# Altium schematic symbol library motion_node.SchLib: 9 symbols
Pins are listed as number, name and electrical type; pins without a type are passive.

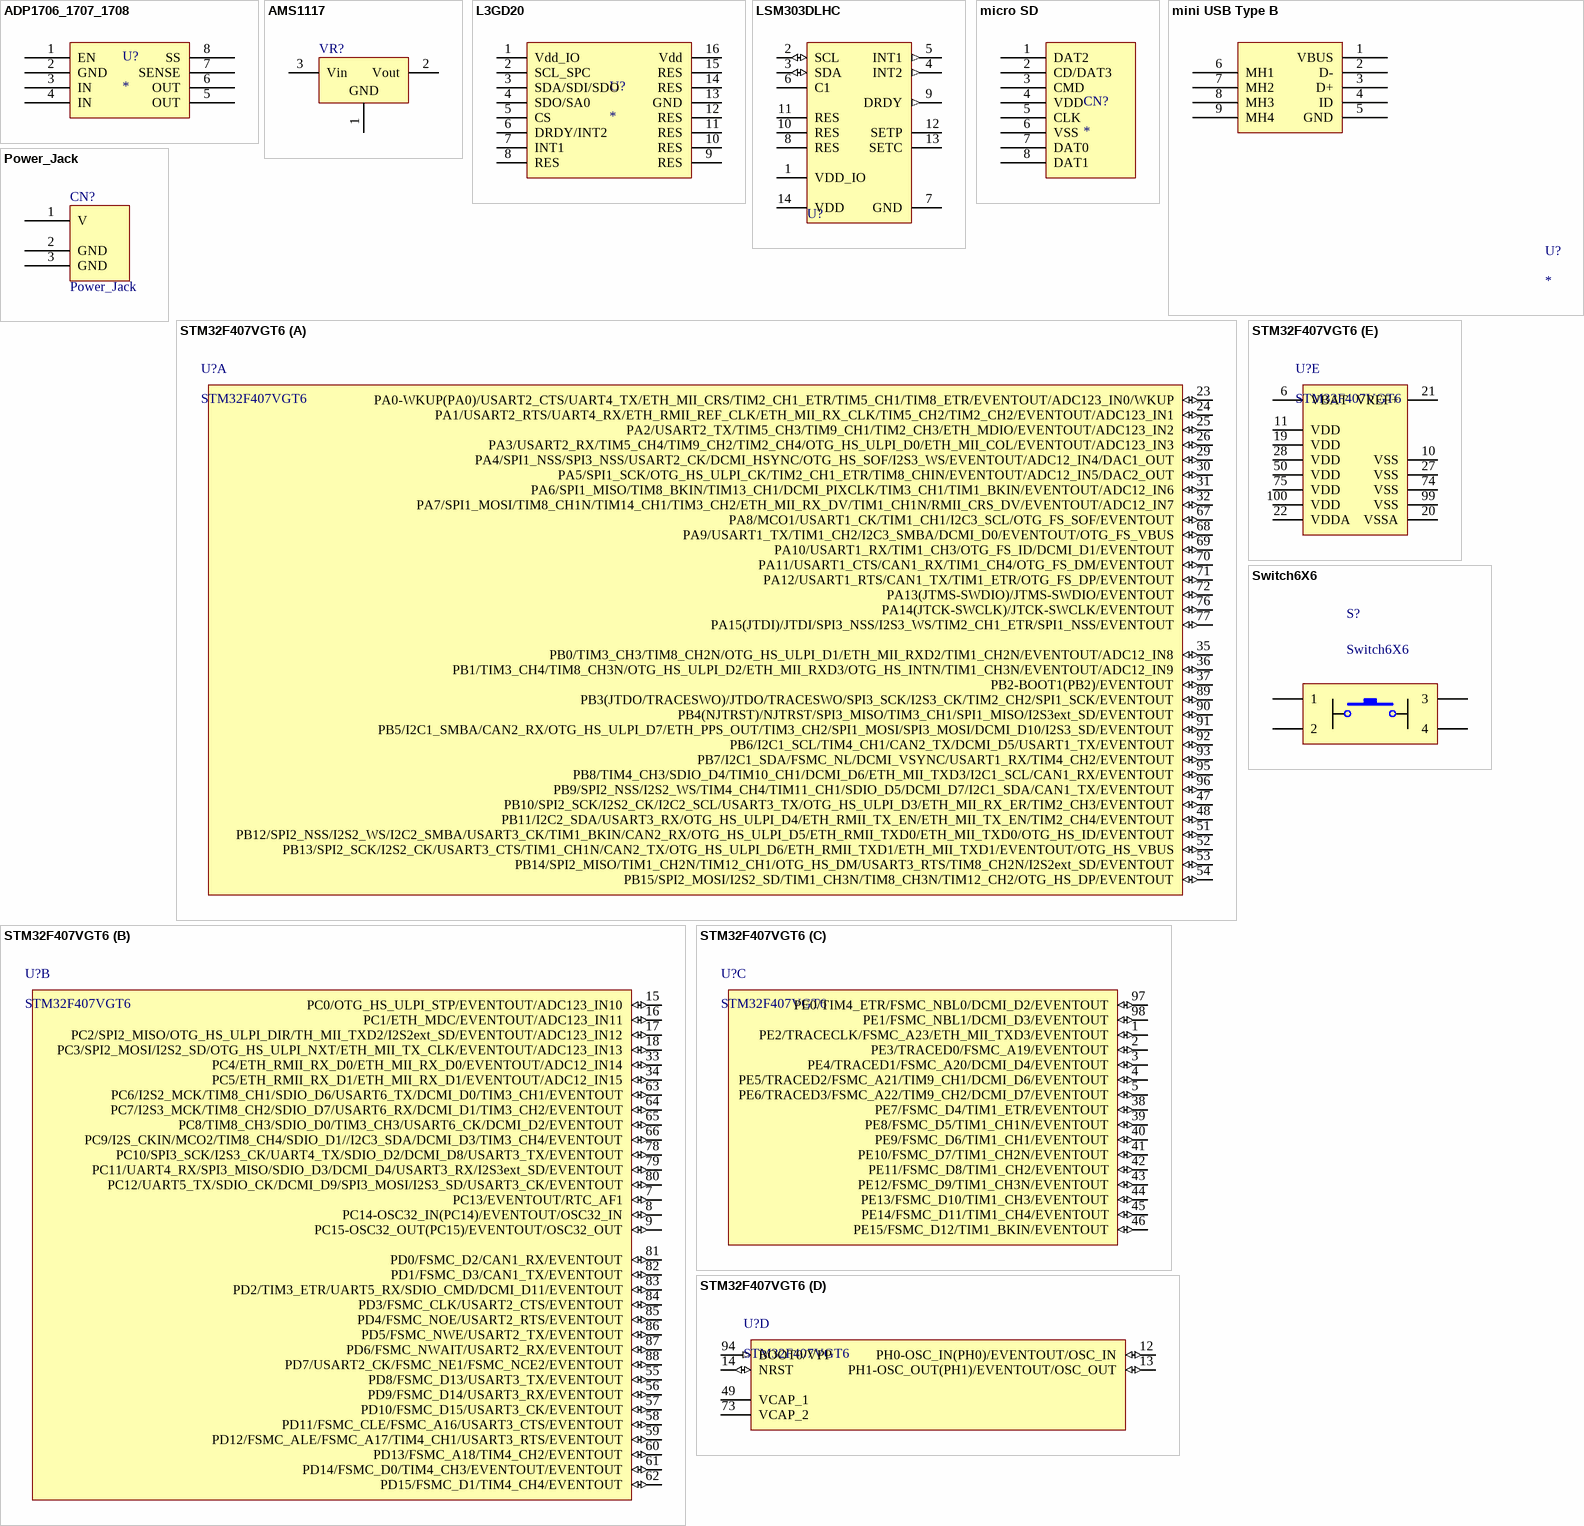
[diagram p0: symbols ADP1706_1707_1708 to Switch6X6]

## ADP1706_1707_1708
designator U?
Linear Regulator
pins: 1 EN, 2 GND, 3 IN, 4 IN, 5 OUT, 6 OUT, 7 SENSE, 8 SS

## AMS1117
designator VR?  (value not drawn)
Voltage Regulator; Code - JEDEC: SMD-220
footprint AMS1117
pins: 1 GND, 2 Vout, 3 Vin

## L3GD20
designator U?
footprint LGA16-4X4X1
pins: 1 Vdd_IO, 2 SCL_SPC, 3 SDA/SDI/SDO, 4 SDO/SA0, 5 CS, 6 DRDY/INT2, 7 INT1, 8 RES, 9 RES, 10 RES, 11 RES, 12 RES, 13 GND, 14 RES, 15 RES, 16 Vdd

## LSM303DLHC
designator U?
footprint LGA14-3X5X1_N (PQFN, 14-Leads, Body 3x5mm, Pitch 0.8mm, IPC Medium Density)
pins: 1 VDD_IO (power), 2 SCL (io), 3 SDA (io), 4 INT2 (out), 5 INT1 (out), 6 C1, 7 GND (power), 8 RES, 9 DRDY (out), 10 RES, 11 RES, 12 SETP, 13 SETC, 14 VDD (power)

## micro SD
designator CN?
footprint micro SD
pins: 1 DAT2, 2 CD/DAT3, 3 CMD, 4 VDD, 5 CLK, 6 VSS, 7 DAT0, 8 DAT1

## mini USB Type B
designator U?
signal-integrity model Mini USB Receptacle (Model Description)
footprint mini USB Type B
pins: 1 VBUS, 2 D-, 3 D+, 4 ID, 5 GND, 6 MH1, 7 MH2, 8 MH3, 9 MH4

## Power_Jack
designator CN?
footprint POWER_JACK
pins: 1 V (power), 2 GND (power), 3 GND (power)

## STM32F407VGT6
designator U?
footprint LQFP100_V (Thin QFP, 100-Leads, Body 14x14mm, Pitch 0.5mm, ST Recommended)
part A pins: 23 PA0-WKUP(PA0)/USART2_CTS/UART4_TX/ETH_MII_CRS/TIM2_CH1_ETR/TIM5_CH1/TIM8_ETR/EVENTOUT/ADC123_IN0/WKUP (io), 24 PA1/USART2_RTS/UART4_RX/ETH_RMII_REF_CLK/ETH_MII_RX_CLK/TIM5_CH2/TIM2_CH2/EVENTOUT/ADC123_IN1 (io), 25 PA2/USART2_TX/TIM5_CH3/TIM9_CH1/TIM2_CH3/ETH_MDIO/EVENTOUT/ADC123_IN2 (io), 26 PA3/USART2_RX/TIM5_CH4/TIM9_CH2/TIM2_CH4/OTG_HS_ULPI_D0/ETH_MII_COL/EVENTOUT/ADC123_IN3 (io), 29 PA4/SPI1_NSS/SPI3_NSS/USART2_CK/DCMI_HSYNC/OTG_HS_SOF/I2S3_WS/EVENTOUT/ADC12_IN4/DAC1_OUT (io), 30 PA5/SPI1_SCK/OTG_HS_ULPI_CK/TIM2_CH1_ETR/TIM8_CHIN/EVENTOUT/ADC12_IN5/DAC2_OUT (io), 31 PA6/SPI1_MISO/TIM8_BKIN/TIM13_CH1/DCMI_PIXCLK/TIM3_CH1/TIM1_BKIN/EVENTOUT/ADC12_IN6 (io), 32 PA7/SPI1_MOSI/TIM8_CH1N/TIM14_CH1/TIM3_CH2/ETH_MII_RX_DV/TIM1_CH1N/RMII_CRS_DV/EVENTOUT/ADC12_IN7 (io), 35 PB0/TIM3_CH3/TIM8_CH2N/OTG_HS_ULPI_D1/ETH_MII_RXD2/TIM1_CH2N/EVENTOUT/ADC12_IN8 (io), 36 PB1/TIM3_CH4/TIM8_CH3N/OTG_HS_ULPI_D2/ETH_MII_RXD3/OTG_HS_INTN/TIM1_CH3N/EVENTOUT/ADC12_IN9 (io), 37 PB2-BOOT1(PB2)/EVENTOUT (io), 47 PB10/SPI2_SCK/I2S2_CK/I2C2_SCL/USART3_TX/OTG_HS_ULPI_D3/ETH_MII_RX_ER/TIM2_CH3/EVENTOUT (io), 48 PB11/I2C2_SDA/USART3_RX/OTG_HS_ULPI_D4/ETH_RMII_TX_EN/ETH_MII_TX_EN/TIM2_CH4/EVENTOUT (io), 51 PB12/SPI2_NSS/I2S2_WS/I2C2_SMBA/USART3_CK/TIM1_BKIN/CAN2_RX/OTG_HS_ULPI_D5/ETH_RMII_TXD0/ETH_MII_TXD0/OTG_HS_ID/EVENTOUT (io), 52 PB13/SPI2_SCK/I2S2_CK/USART3_CTS/TIM1_CH1N/CAN2_TX/OTG_HS_ULPI_D6/ETH_RMII_TXD1/ETH_MII_TXD1/EVENTOUT/OTG_HS_VBUS (io), 53 PB14/SPI2_MISO/TIM1_CH2N/TIM12_CH1/OTG_HS_DM/USART3_RTS/TIM8_CH2N/I2S2ext_SD/EVENTOUT (io), 54 PB15/SPI2_MOSI/I2S2_SD/TIM1_CH3N/TIM8_CH3N/TIM12_CH2/OTG_HS_DP/EVENTOUT (io), 67 PA8/MCO1/USART1_CK/TIM1_CH1/I2C3_SCL/OTG_FS_SOF/EVENTOUT (io), 68 PA9/USART1_TX/TIM1_CH2/I2C3_SMBA/DCMI_D0/EVENTOUT/OTG_FS_VBUS (io), 69 PA10/USART1_RX/TIM1_CH3/OTG_FS_ID/DCMI_D1/EVENTOUT (io), 70 PA11/USART1_CTS/CAN1_RX/TIM1_CH4/OTG_FS_DM/EVENTOUT (io), 71 PA12/USART1_RTS/CAN1_TX/TIM1_ETR/OTG_FS_DP/EVENTOUT (io), 72 PA13(JTMS-SWDIO)/JTMS-SWDIO/EVENTOUT (io), 76 PA14(JTCK-SWCLK)/JTCK-SWCLK/EVENTOUT (io), 77 PA15(JTDI)/JTDI/SPI3_NSS/I2S3_WS/TIM2_CH1_ETR/SPI1_NSS/EVENTOUT (io), 89 PB3(JTDO/TRACESWO)/JTDO/TRACESWO/SPI3_SCK/I2S3_CK/TIM2_CH2/SPI1_SCK/EVENTOUT (io), 90 PB4(NJTRST)/NJTRST/SPI3_MISO/TIM3_CH1/SPI1_MISO/I2S3ext_SD/EVENTOUT (io), 91 PB5/I2C1_SMBA/CAN2_RX/OTG_HS_ULPI_D7/ETH_PPS_OUT/TIM3_CH2/SPI1_MOSI/SPI3_MOSI/DCMI_D10/I2S3_SD/EVENTOUT (io), 92 PB6/I2C1_SCL/TIM4_CH1/CAN2_TX/DCMI_D5/USART1_TX/EVENTOUT (io), 93 PB7/I2C1_SDA/FSMC_NL/DCMI_VSYNC/USART1_RX/TIM4_CH2/EVENTOUT (io), 95 PB8/TIM4_CH3/SDIO_D4/TIM10_CH1/DCMI_D6/ETH_MII_TXD3/I2C1_SCL/CAN1_RX/EVENTOUT (io), 96 PB9/SPI2_NSS/I2S2_WS/TIM4_CH4/TIM11_CH1/SDIO_D5/DCMI_D7/I2C1_SDA/CAN1_TX/EVENTOUT (io)
part B pins: 7 PC13/EVENTOUT/RTC_AF1 (io), 8 PC14-OSC32_IN(PC14)/EVENTOUT/OSC32_IN (io), 9 PC15-OSC32_OUT(PC15)/EVENTOUT/OSC32_OUT (io), 15 PC0/OTG_HS_ULPI_STP/EVENTOUT/ADC123_IN10 (io), 16 PC1/ETH_MDC/EVENTOUT/ADC123_IN11 (io), 17 PC2/SPI2_MISO/OTG_HS_ULPI_DIR/TH_MII_TXD2/I2S2ext_SD/EVENTOUT/ADC123_IN12 (io), 18 PC3/SPI2_MOSI/I2S2_SD/OTG_HS_ULPI_NXT/ETH_MII_TX_CLK/EVENTOUT/ADC123_IN13 (io), 33 PC4/ETH_RMII_RX_D0/ETH_MII_RX_D0/EVENTOUT/ADC12_IN14 (io), 34 PC5/ETH_RMII_RX_D1/ETH_MII_RX_D1/EVENTOUT/ADC12_IN15 (io), 55 PD8/FSMC_D13/USART3_TX/EVENTOUT (io), 56 PD9/FSMC_D14/USART3_RX/EVENTOUT (io), 57 PD10/FSMC_D15/USART3_CK/EVENTOUT (io), 58 PD11/FSMC_CLE/FSMC_A16/USART3_CTS/EVENTOUT (io), 59 PD12/FSMC_ALE/FSMC_A17/TIM4_CH1/USART3_RTS/EVENTOUT (io), 60 PD13/FSMC_A18/TIM4_CH2/EVENTOUT (io), 61 PD14/FSMC_D0/TIM4_CH3/EVENTOUT/EVENTOUT (io), 62 PD15/FSMC_D1/TIM4_CH4/EVENTOUT (io), 63 PC6/I2S2_MCK/TIM8_CH1/SDIO_D6/USART6_TX/DCMI_D0/TIM3_CH1/EVENTOUT (io), 64 PC7/I2S3_MCK/TIM8_CH2/SDIO_D7/USART6_RX/DCMI_D1/TIM3_CH2/EVENTOUT (io), 65 PC8/TIM8_CH3/SDIO_D0/TIM3_CH3/USART6_CK/DCMI_D2/EVENTOUT (io), 66 PC9/I2S_CKIN/MCO2/TIM8_CH4/SDIO_D1//I2C3_SDA/DCMI_D3/TIM3_CH4/EVENTOUT (io), 78 PC10/SPI3_SCK/I2S3_CK/UART4_TX/SDIO_D2/DCMI_D8/USART3_TX/EVENTOUT (io), 79 PC11/UART4_RX/SPI3_MISO/SDIO_D3/DCMI_D4/USART3_RX/I2S3ext_SD/EVENTOUT (io), 80 PC12/UART5_TX/SDIO_CK/DCMI_D9/SPI3_MOSI/I2S3_SD/USART3_CK/EVENTOUT (io), 81 PD0/FSMC_D2/CAN1_RX/EVENTOUT (io), 82 PD1/FSMC_D3/CAN1_TX/EVENTOUT (io), 83 PD2/TIM3_ETR/UART5_RX/SDIO_CMD/DCMI_D11/EVENTOUT (io), 84 PD3/FSMC_CLK/USART2_CTS/EVENTOUT (io), 85 PD4/FSMC_NOE/USART2_RTS/EVENTOUT (io), 86 PD5/FSMC_NWE/USART2_TX/EVENTOUT (io), 87 PD6/FSMC_NWAIT/USART2_RX/EVENTOUT (io), 88 PD7/USART2_CK/FSMC_NE1/FSMC_NCE2/EVENTOUT (io)
part C pins: 1 PE2/TRACECLK/FSMC_A23/ETH_MII_TXD3/EVENTOUT (io), 2 PE3/TRACED0/FSMC_A19/EVENTOUT (io), 3 PE4/TRACED1/FSMC_A20/DCMI_D4/EVENTOUT (io), 4 PE5/TRACED2/FSMC_A21/TIM9_CH1/DCMI_D6/EVENTOUT (io), 5 PE6/TRACED3/FSMC_A22/TIM9_CH2/DCMI_D7/EVENTOUT (io), 38 PE7/FSMC_D4/TIM1_ETR/EVENTOUT (io), 39 PE8/FSMC_D5/TIM1_CH1N/EVENTOUT (io), 40 PE9/FSMC_D6/TIM1_CH1/EVENTOUT (io), 41 PE10/FSMC_D7/TIM1_CH2N/EVENTOUT (io), 42 PE11/FSMC_D8/TIM1_CH2/EVENTOUT (io), 43 PE12/FSMC_D9/TIM1_CH3N/EVENTOUT (io), 44 PE13/FSMC_D10/TIM1_CH3/EVENTOUT (io), 45 PE14/FSMC_D11/TIM1_CH4/EVENTOUT (io), 46 PE15/FSMC_D12/TIM1_BKIN/EVENTOUT (io), 97 PE0/TIM4_ETR/FSMC_NBL0/DCMI_D2/EVENTOUT (io), 98 PE1/FSMC_NBL1/DCMI_D3/EVENTOUT (io)
part D pins: 12 PH0-OSC_IN(PH0)/EVENTOUT/OSC_IN (io), 13 PH1-OSC_OUT(PH1)/EVENTOUT/OSC_OUT (io), 14 NRST (io), 49 VCAP_1 (power), 73 VCAP_2 (power), 94 BOOT0/VPP (in)
part E pins: 6 VBAT (power), 10 VSS (power), 11 VDD (power), 19 VDD (power), 20 VSSA (power), 21 VREF+ (power), 22 VDDA (power), 27 VSS (power), 28 VDD (power), 50 VDD (power), 74 VSS (power), 75 VDD (power), 99 VSS (power), 100 VDD (power)

## Switch6X6
designator S?
Switch
footprint Switch6X6
pins: 1, 2, 3, 4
